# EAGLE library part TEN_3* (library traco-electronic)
DC/DC Konverter 3 Watt, 2 x Input, 1 x Output Source: http://www.tracopower.com/datasheet_g/ten3-d.pdf
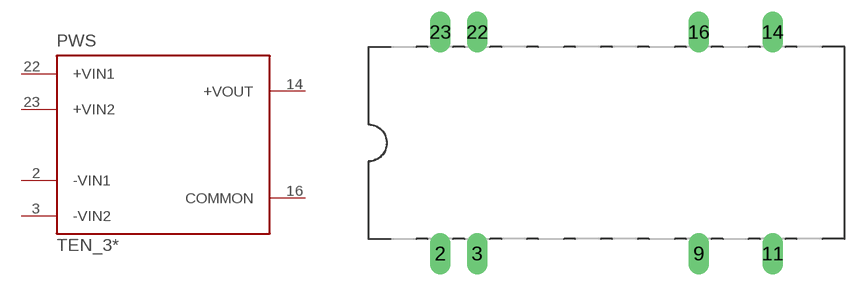
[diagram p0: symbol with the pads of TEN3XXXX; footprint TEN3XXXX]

Designator prefix PWS

## TEN_30510 (OC_FARNELL: unknown; OC_NEWARK: unknown), TEN_30511 (OC_FARNELL: unknown; OC_NEWARK: unknown), TEN_30512 (OC_FARNELL: unknown; OC_NEWARK: unknown), TEN_30513 (OC_FARNELL: unknown; OC_NEWARK: unknown), TEN_31210 (OC_FARNELL: unknown; OC_NEWARK: unknown), TEN_31211 (OC_FARNELL: unknown; OC_NEWARK: unknown), TEN_31212 (OC_FARNELL: unknown; OC_NEWARK: unknown), TEN_31213 (OC_FARNELL: unknown; OC_NEWARK: unknown), TEN_32410 (OC_FARNELL: unknown; OC_NEWARK: unknown), TEN_32411 (MPN: TEN3-2411; OC_FARNELL: unknown; OC_NEWARK: 45K1582), TEN_32412 (OC_FARNELL: unknown; OC_NEWARK: unknown), TEN_32413 (MPN: TEN3-2413; OC_FARNELL: unknown; OC_NEWARK: 14N5516), TEN_34810 (OC_FARNELL: unknown; OC_NEWARK: unknown), TEN_34811 (MPN: TEN 3-4811WI; OC_FARNELL: unknown; OC_NEWARK: 90R9814), TEN_34812 (OC_FARNELL: unknown; OC_NEWARK: unknown), TEN_34813 (OC_FARNELL: unknown; OC_NEWARK: unknown)  [TEN3XXXX]
2  -VIN1  in
3  -VIN2  in
14  +VOUT  pas
16  COMMON  pas
22  +VIN1  in
23  +VIN2  in

## Footprint TEN3XXXX (pad centres in mm)
DC/DC Konverter 3 Watt Source: http://www.tracopower.com/datasheet_g/ten3-d.pdf
drill 0.813 pad 1.422 long: 2 -11.43,-7.62; 3 -8.89,-7.62; 9 6.35,-7.62; 11 11.43,-7.62; 14 11.43,7.62; 16 6.35,7.62; 22 -8.89,7.62; 23 -11.43,7.62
